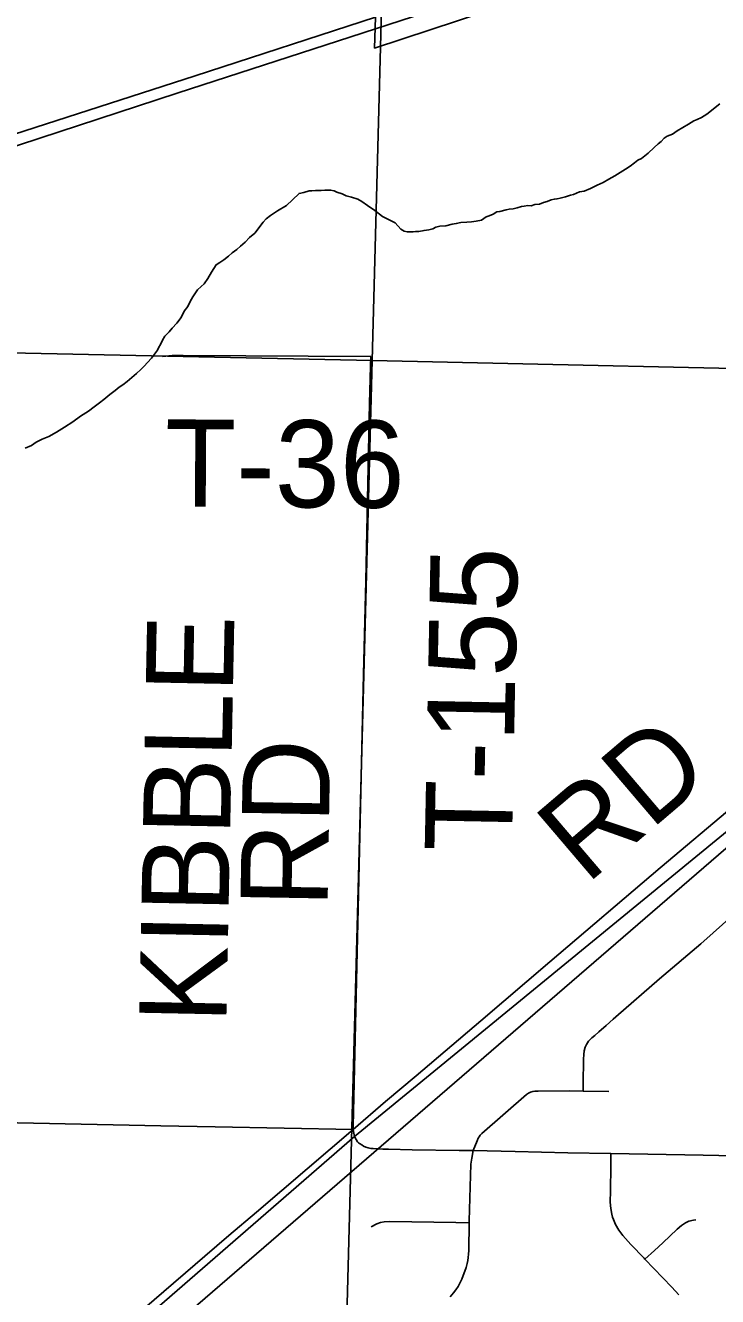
# Model space of a CAD drawing. Extents: x 0 to 34, y 0 to 22.
# Drawn here: x 4.185 to 4.636, y 16.822 to 17.65 of the extents above; entities that cross this region are included whole.
import ezdxf

# ---------------------------------------------------------------- set-up
doc = ezdxf.new("R2010")
doc.units = 0
for name, color, linetype in [('Default', 7, 'Continuous'), ('GM_X_City_Street', 7, 'Continuous'), ('GM_X_County_Road', 7, 'Continuous'), ('GM_X_County_Road_Text', 7, 'Continuous'), ('GM_X_Minor_River', 7, 'Continuous'), ('GM_X_Rail_Line', 7, 'Continuous'), ('GM_X_Section', 7, 'Continuous'), ('GM_X_Township_Road', 7, 'Continuous'), ('GM_X_Township_Road_Text', 7, 'Continuous')]:
    doc.layers.add(name, color=color, linetype=linetype)

msp = doc.modelspace()

# ---------------------------------------------------------------- linework, layer by layer
at = {"layer": 'Default'}
for points in [[(2.38399, 16.99985), (4.29581, 17.61729), (4.4133, 17.65564), (4.41266, 17.63545), (4.52142, 17.67154)], [(4.91492, 17.65219), (4.91134, 17.55474), (4.66262, 17.55784), (4.65986, 17.431), (4.88423, 17.43136), (4.91579, 17.43085), (5.01519, 17.43039), (4.39952, 16.92604), (4.21794, 16.76833)]]:
    msp.add_lwpolyline(points, dxfattribs=at)
at = {"layer": 'GM_X_City_Street'}
for points in [[(4.54858, 16.95551), (4.54864, 16.9628), (4.54872, 16.97391), (4.54885, 16.97637), (4.54902, 16.97942), (4.54925, 16.98189), (4.54987, 16.9843), (4.55064, 16.98598), (4.55207, 16.98801), (4.55423, 16.99023), (4.55605, 16.99186), (4.55885, 16.99428), (4.56354, 16.99836), (4.56806, 17.00242), (4.56985, 17.00398), (4.59828, 17.02871), (4.62521, 17.0516), (4.64728, 17.07123)], [(4.47683, 16.91685), (4.47938, 16.9231), (4.4802, 16.92483), (4.48078, 16.92582), (4.48143, 16.92681), (4.4825, 16.92796), (4.5116, 16.9534), (4.513, 16.9543), (4.51431, 16.95488), (4.51579, 16.95529), (4.51718, 16.95555), (4.51924, 16.95562), (4.53948, 16.95564), (4.54858, 16.95551), (4.56527, 16.95529)], [(4.39858, 16.93054), (4.39926, 16.92703), (4.39975, 16.92548), (4.40053, 16.92394), (4.40151, 16.92253), (4.40212, 16.92194), (4.40278, 16.92139), (4.40423, 16.92046), (4.40549, 16.91972), (4.40703, 16.91903), (4.40851, 16.91854), (4.41013, 16.91819), (4.41176, 16.91805), (4.41811, 16.9178), (4.42161, 16.91762), (4.43719, 16.91726), (4.46766, 16.91694), (4.47683, 16.91685), (4.50432, 16.91623), (4.5385, 16.91543), (4.56663, 16.91491), (4.62676, 16.91383), (4.64725, 16.91342)], [(4.46191, 16.82147), (4.46408, 16.82398), (4.4656, 16.82599), (4.46708, 16.82829), (4.46827, 16.83043), (4.46951, 16.83294), (4.47044, 16.83537), (4.47151, 16.83825), (4.47225, 16.8406), (4.47295, 16.84315), (4.47336, 16.84525), (4.47361, 16.84709), (4.47389, 16.84935), (4.47405, 16.85174), (4.47435, 16.86968), (4.47437, 16.8709), (4.47541, 16.90792), (4.47593, 16.91192), (4.47683, 16.91685)], [(4.61099, 16.82281), (4.60628, 16.82775), (4.58883, 16.84594), (4.58822, 16.84658), (4.57966, 16.85554), (4.57432, 16.86151), (4.57182, 16.86494), (4.56969, 16.86861), (4.56825, 16.87192), (4.5677, 16.87349), (4.5672, 16.87539), (4.56653, 16.87894), (4.56618, 16.88317), (4.56625, 16.89057), (4.5665, 16.90673), (4.56663, 16.91491)], [(4.41037, 16.86706), (4.41416, 16.86896), (4.41642, 16.86987), (4.41878, 16.87034), (4.4225, 16.87054), (4.46549, 16.86983), (4.47435, 16.86968)], [(4.58883, 16.84594), (4.59493, 16.8516), (4.60037, 16.85665), (4.60977, 16.86566), (4.61263, 16.86802), (4.61522, 16.86969), (4.61748, 16.87069), (4.62047, 16.87154), (4.62186, 16.87175)]]:
    msp.add_lwpolyline(points, dxfattribs=at)
at = {"layer": 'GM_X_County_Road'}
for points in [[(4.39858, 16.93054), (4.41975, 16.94873), (4.43969, 16.9656), (4.48185, 17.00144), (4.52672, 17.03987), (4.59876, 17.10104), (4.6467, 17.14161)], [(4.21426, 16.77255), (4.22709, 16.78367), (4.24226, 16.79654), (4.3021, 16.84807), (4.31769, 16.86143), (4.33577, 16.87663), (4.36881, 16.90497), (4.39858, 16.93054)]]:
    msp.add_lwpolyline(points, dxfattribs=at)
at = {"layer": 'GM_X_Minor_River'}
for points in [[(3.74301, 16.33754), (5.62913, 17.96708)], [(4.6376, 17.59907), (4.63566, 17.5976), (4.63217, 17.59465), (4.62907, 17.59245), (4.6256, 17.59026), (4.6229, 17.58881), (4.62061, 17.58811), (4.61714, 17.58592), (4.60981, 17.58154), (4.60671, 17.57934), (4.60326, 17.57791), (4.60133, 17.57682), (4.59938, 17.57459), (4.59744, 17.57312), (4.59472, 17.57053), (4.59083, 17.56683), (4.58657, 17.56352), (4.58426, 17.56244), (4.58193, 17.5606), (4.57922, 17.55839), (4.57614, 17.55657), (4.57266, 17.55438), (4.56919, 17.55219), (4.56534, 17.55001), (4.56148, 17.54782), (4.55764, 17.54602), (4.5534, 17.54385), (4.54918, 17.54206), (4.54614, 17.54176), (4.54229, 17.53995), (4.54039, 17.53962), (4.53694, 17.53857), (4.5335, 17.53752), (4.53159, 17.53719), (4.52968, 17.53685), (4.52777, 17.53652), (4.52509, 17.53545), (4.52279, 17.53475), (4.5201, 17.53368), (4.51706, 17.53338), (4.51476, 17.53267), (4.51248, 17.53273), (4.5102, 17.53241), (4.50829, 17.53208), (4.50561, 17.53139), (4.50293, 17.5307), (4.50027, 17.53038), (4.49836, 17.53005), (4.49416, 17.52902), (4.49225, 17.52869), (4.48993, 17.52723), (4.48725, 17.52615), (4.48533, 17.52544), (4.48224, 17.52324), (4.4788, 17.52257), (4.47575, 17.52227), (4.47271, 17.52196), (4.4689, 17.52168), (4.46585, 17.521), (4.46318, 17.52069), (4.45897, 17.51965), (4.45517, 17.51937), (4.45249, 17.51868), (4.45057, 17.51759), (4.44789, 17.51689), (4.44484, 17.51659), (4.44141, 17.51592), (4.43951, 17.51597), (4.4376, 17.51564), (4.43381, 17.51573), (4.43192, 17.51616), (4.42967, 17.51736), (4.42598, 17.52163), (4.41772, 17.52564), (4.41288, 17.52956), (4.40802, 17.53272), (4.40429, 17.53547), (4.40167, 17.53706), (4.39753, 17.5383), (4.39413, 17.53915), (4.3915, 17.54035), (4.38811, 17.54158), (4.38623, 17.54239)], [(4.38623, 17.54239), (4.38396, 17.54282), (4.38017, 17.54292), (4.37788, 17.5426), (4.37598, 17.54264), (4.37408, 17.54269), (4.3718, 17.54237), (4.3699, 17.54242), (4.36645, 17.54137), (4.36339, 17.54069), (4.35912, 17.53662), (4.35523, 17.53292), (4.34944, 17.52927), (4.34481, 17.52634), (4.34209, 17.52413), (4.34013, 17.5219), (4.33857, 17.52004), (4.33621, 17.51668), (4.33464, 17.51483), (4.33115, 17.51188), (4.32841, 17.50891), (4.32531, 17.50633), (4.32297, 17.50411), (4.31988, 17.50191), (4.31755, 17.49969), (4.31445, 17.49748), (4.31175, 17.49565), (4.30943, 17.49419), (4.30627, 17.48934), (4.30389, 17.48522), (4.30153, 17.48186), (4.29958, 17.48001), (4.29725, 17.47779), (4.2941, 17.47331), (4.2925, 17.47031), (4.2909, 17.46694), (4.28854, 17.46396), (4.28654, 17.45983), (4.28379, 17.4561), (4.28067, 17.45276), (4.27871, 17.45053), (4.27598, 17.44756), (4.27439, 17.44494), (4.27319, 17.44231), (4.272, 17.44045), (4.27119, 17.43857), (4.26923, 17.43596), (4.26726, 17.43335), (4.26219, 17.42778), (4.26024, 17.42593), (4.25752, 17.42334), (4.25442, 17.42076), (4.25131, 17.41818), (4.2486, 17.41597), (4.24628, 17.41451), (4.24357, 17.4123), (4.24009, 17.40973), (4.2362, 17.40641), (4.23349, 17.4042), (4.23, 17.40163), (4.22614, 17.39869), (4.22111, 17.3954), (4.21608, 17.39173), (4.21068, 17.38844), (4.20528, 17.38516), (4.20027, 17.38225), (4.19605, 17.38046), (4.19221, 17.37866), (4.18911, 17.37646), (4.18489, 17.37466)]]:
    msp.add_lwpolyline(points, dxfattribs=at)
at = {"layer": 'GM_X_Rail_Line'}
msp.add_lwpolyline([(2.38289, 16.983), (4.2841, 17.60614), (4.99507, 17.83701), (5.08648, 17.869), (5.17577, 17.90296), (5.27433, 17.95087), (5.35859, 17.99218), (5.42907, 18.02958)], dxfattribs=at)
at = {"layer": 'GM_X_Section'}
for points in [[(3.42832, 18.47555), (4.43788, 18.43754), (4.41097, 17.43188), (3.40485, 17.45313)], [(4.43788, 18.43754), (5.43503, 18.42215), (5.41251, 17.40958), (4.41097, 17.43188)], [(3.40485, 17.45313), (4.41097, 17.43188), (4.38456, 16.43152), (3.38639, 16.45221), (3.37427, 16.45247)], [(4.41097, 17.43188), (5.41251, 17.40958), (5.38574, 16.41038), (5.38005, 16.41012), (4.38456, 16.43152)]]:
    msp.add_lwpolyline(points, close=True, dxfattribs=at)
at = {"layer": 'GM_X_Township_Road'}
for points in [[(4.2744, 17.43432), (4.28077, 17.43499), (4.2879, 17.43515), (4.41013, 17.43445)], [(4.39858, 16.93054), (4.39863, 16.93262), (4.40332, 17.1316), (4.40549, 17.2273), (4.40689, 17.2882), (4.40779, 17.33108), (4.40931, 17.40379), (4.40996, 17.42802), (4.41013, 17.43445)], [(3.39264, 16.95417), (3.39707, 16.95415), (3.40826, 16.95409), (3.46108, 16.95279), (3.49587, 16.95187), (3.53316, 16.95085), (3.59592, 16.94933), (3.70219, 16.9469), (3.73823, 16.9461), (3.77427, 16.94518), (3.91781, 16.94118), (4.00729, 16.93901), (4.04644, 16.93799), (4.08124, 16.93726), (4.16948, 16.9352), (4.2422, 16.93362), (4.27327, 16.93294), (4.3087, 16.93223), (4.39858, 16.93054)]]:
    msp.add_lwpolyline(points, dxfattribs=at)

# ---------------------------------------------------------------- texts
at = {"layer": 'GM_X_County_Road_Text'}
msp.add_text('RD', height=0.056818, rotation=40.43993, dxfattribs=at).set_placement((4.55065, 17.08975))
at = {"layer": 'GM_X_Township_Road_Text'}
for s, rotation, p in [('T-36', 359.64418, (4.27588, 17.33664)), ('T-155', 88.87745, (4.50208, 17.11124)), ('KIBBLE', 88.85775, (4.316, 16.99929)), ('RD', 89.01275, (4.38197, 17.07488))]:
    msp.add_text(s, height=0.056818, rotation=rotation, dxfattribs=at).set_placement(p)

doc.saveas('drawing.dxf')
